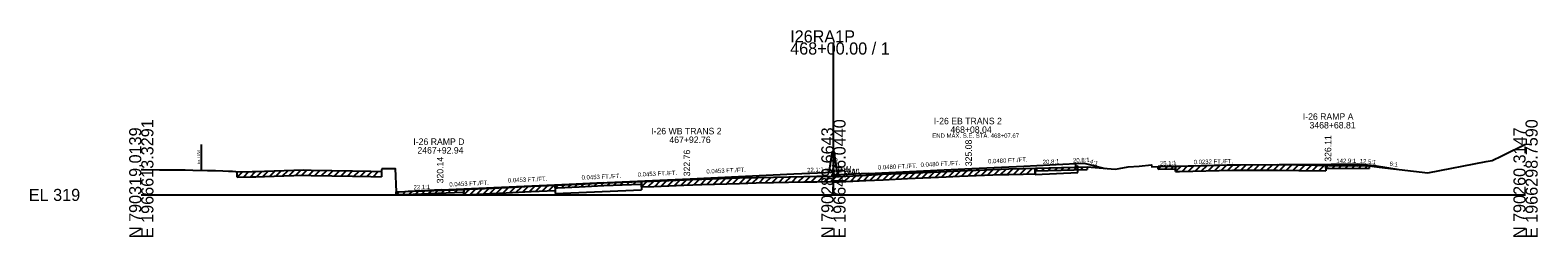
# Model space of a CAD drawing. Extents: x -44 to 4323, y -10 to 9601.
# Drawn here: x 3974.3 to 4322.8, y 6490.3 to 6538.1 of the extents above; entities that cross this region are included whole.
import ezdxf

# ---------------------------------------------------------------- set-up
doc = ezdxf.new("R2010")
doc.units = 0
for name, color, linetype in [('1', 7, 'Continuous'), ('DateStamp', 7, 'Continuous'), ('NotForConst', 7, 'Continuous'), ('QCQA', 7, 'Continuous'), ('RD_SHT_Bndy', 7, 'Continuous'), ('RD_SHT_Iplotshp', 7, 'Continuous'), ('RD_SHT_TX', 7, 'Continuous'), ('RD_XS_ExGround', 7, 'Continuous'), ('RD_XS_MatchLine', 7, 'Continuous'), ('RD_XS_MedBWall', 7, 'Continuous'), ('RD_XS_Misc_Line', 7, 'Continuous'), ('RD_XS_Pave', 7, 'Continuous'), ('RD_XS_PaveOvlay', 7, 'Continuous'), ('RD_XS_PaveShd', 7, 'Continuous'), ('RD_XS_TX_Elev_PR', 7, 'Continuous'), ('RD_XS_TX_Profile', 7, 'Continuous'), ('RD_XS_TX_ShdSlope', 7, 'Continuous'), ('RD_XS_TX_Slope', 7, 'Continuous'), ('seal', 7, 'Continuous'), ('TR SN EXTRUDED PANEL SIGNS - GROUND MOUNTED', 7, 'Continuous')]:
    doc.layers.add(name, color=color, linetype=linetype)

msp = doc.modelspace()

# ---------------------------------------------------------------- linework, layer by layer
at = {"layer": 'DateStamp'}
msp.add_lwpolyline([(4000, 6505.86), (4000.57, 6505.85), (4004.17, 6505.83), (4007.8, 6505.8), (4010.17, 6505.77), (4011.88, 6505.75), (4015.27, 6505.65), (4017.19, 6505.61), (4018.84, 6505.56), (4020.14, 6505.5), (4021.1, 6505.45), (4021.75, 6505.4), (4022.13, 6505.36), (4025.63, 6505.39), (4026.5, 6505.41), (4028.48, 6505.49), (4037.5, 6505.8), (4039.26, 6505.74), (4048.83, 6505.56), (4053.03, 6505.47), (4055.56, 6505.44), (4055.71, 6506.12), (4056.83, 6506.12), (4058.71, 6506.12), (4058.93, 6500.69), (4062.86, 6500.83), (4072.41, 6501.17), (4077.69, 6501.42), (4084.36, 6501.72), (4090.12, 6502), (4096.19, 6502.29), (4101.26, 6502.52), (4106.94, 6502.77), (4113.35, 6503.02), (4118.47, 6503.21), (4125.45, 6503.47), (4129.55, 6503.63), (4138.29, 6503.91), (4142.12, 6504.04), (4146.18, 6504.12), (4153.12, 6504.26), (4156.19, 6504.31), (4158.54, 6504.35), (4160.05, 6504.29), (4161.32, 6504.24), (4164.47, 6504.41), (4167.46, 6504.57), (4171.52, 6504.77), (4177.13, 6505.04), (4186.09, 6505.44), (4189.16, 6505.58), (4198.79, 6505.93), (4200.54, 6505.99), (4203.87, 6506.08), (4218.62, 6506.48), (4222.32, 6506.16), (4225.15, 6505.95), (4226.04, 6506.09), (4228.17, 6506.47), (4230.7, 6506.66), (4233.54, 6506.95), (4233.64, 6506.5), (4235.08, 6506.54), (4239.2, 6506.66), (4239.99, 6506.67), (4252.22, 6506.97), (4254.1, 6506.97), (4262.68, 6507), (4267.56, 6506.92), (4267.9, 6506.92), (4274.59, 6506.83), (4283.87, 6506.71), (4286.13, 6506.44), (4297.43, 6505.09), (4310.86, 6507.7), (4312.28, 6507.94), (4314.5, 6509.04), (4320, 6511.75)], dxfattribs=at)
at = {"layer": 'NotForConst'}
for p, q in [((4022.13, 6504.11), (4023.39, 6505.37)), ((4023.63, 6504.12), (4024.89, 6505.38)), ((4025.13, 6504.13), (4026.41, 6505.41)), ((4026.63, 6504.17), (4027.93, 6505.47)), ((4028.13, 6504.23), (4029.42, 6505.53)), ((4029.63, 6504.28), (4030.92, 6505.58)), ((4031.13, 6504.33), (4032.42, 6505.63)), ((4032.63, 6504.39), (4033.92, 6505.68)), ((4034.13, 6504.44), (4035.42, 6505.73)), ((4035.63, 6504.49), (4036.92, 6505.78)), ((4037.13, 6504.54), (4038.36, 6505.77)), ((4038.63, 6504.51), (4039.85, 6505.73)), ((4040.13, 6504.48), (4041.36, 6505.7)), ((4041.63, 6504.45), (4042.86, 6505.67)), ((4043.13, 6504.42), (4044.36, 6505.64)), ((4044.63, 6504.39), (4045.86, 6505.61)), ((4046.13, 6504.36), (4047.36, 6505.58)), ((4047.63, 6504.33), (4048.86, 6505.55)), ((4049.13, 6504.3), (4050.36, 6505.52)), ((4050.63, 6504.27), (4051.86, 6505.49)), ((4052.13, 6504.24), (4053.36, 6505.47)), ((4053.63, 6504.21), (4054.86, 6505.45)), ((4129.24, 6502.36), (4130.54, 6503.66)), ((4130.75, 6502.42), (4132.05, 6503.71)), ((4132.26, 6502.47), (4133.56, 6503.76)), ((4133.77, 6502.52), (4135.07, 6503.81)), ((4135.27, 6502.57), (4136.58, 6503.86)), ((4136.78, 6502.62), (4138.08, 6503.91)), ((4138.29, 6502.66), (4139.59, 6503.96)), ((4139.8, 6502.72), (4141.1, 6504.01)), ((4141.31, 6502.77), (4142.6, 6504.05)), ((4142.82, 6502.81), (4144.1, 6504.08)), ((4144.33, 6502.84), (4145.61, 6504.11)), ((4145.84, 6502.87), (4147.12, 6504.14)), ((4147.35, 6502.9), (4148.63, 6504.17)), ((4148.86, 6502.93), (4150.14, 6504.2)), ((4150.36, 6502.96), (4151.65, 6504.23)), ((4151.87, 6502.99), (4153.16, 6504.26)), ((4153.38, 6503.02), (4154.66, 6504.29)), ((4154.89, 6503.04), (4156.17, 6504.31)), ((4156.4, 6503.06), (4157.68, 6504.34)), ((4157.91, 6503.09), (4159.15, 6504.33)), ((4159.42, 6503.07), (4160.62, 6504.27)), ((4160.93, 6503), (4162.21, 6504.28)), ((4162.44, 6503.05), (4163.77, 6504.37)), ((4163.94, 6503.13), (4165.27, 6504.45)), ((4165.45, 6503.21), (4166.78, 6504.53)), ((4166.96, 6503.29), (4168.29, 6504.61)), ((4168.47, 6503.37), (4169.79, 6504.68)), ((4169.98, 6503.44), (4171.3, 6504.76)), ((4171.49, 6503.52), (4172.81, 6504.83)), ((4173, 6503.59), (4174.32, 6504.9)), ((4174.51, 6503.66), (4175.83, 6504.97)), ((4176.02, 6503.73), (4177.34, 6505.05)), ((4177.52, 6503.8), (4178.84, 6505.11)), ((4179.03, 6503.87), (4180.35, 6505.18)), ((4180.54, 6503.94), (4181.86, 6505.25)), ((4182.05, 6504.01), (4183.37, 6505.32)), ((4183.56, 6504.08), (4184.88, 6505.38)), ((4185.07, 6504.14), (4186.39, 6505.45)), ((4186.58, 6504.21), (4187.9, 6505.52)), ((4188.09, 6504.28), (4189.4, 6505.59)), ((4189.6, 6504.34), (4190.9, 6505.64)), ((4191.11, 6504.4), (4192.41, 6505.7)), ((4192.61, 6504.46), (4193.92, 6505.75)), ((4194.12, 6504.51), (4195.43, 6505.81)), ((4195.63, 6504.57), (4196.94, 6505.87)), ((4197.14, 6504.62), (4198.45, 6505.92)), ((4198.65, 6504.68), (4199.95, 6505.97)), ((4200.16, 6504.73), (4201.45, 6506.01)), ((4201.67, 6504.77), (4202.96, 6506.05)), ((4203.18, 6504.81), (4204.47, 6506.09)), ((4204.69, 6504.85), (4205.98, 6506.13)), ((4206.61, 6505.53), (4207.26, 6506.17)), ((4208.11, 6505.57), (4208.76, 6506.21)), ((4209.61, 6505.61), (4210.26, 6506.25)), ((4211.11, 6505.65), (4211.76, 6506.29)), ((4212.61, 6505.69), (4213.26, 6506.33)), ((4214.12, 6505.73), (4214.76, 6506.37)), ((4215.62, 6505.77), (4216.26, 6506.41)), ((4217.12, 6505.81), (4217.76, 6506.45)), ((4235.08, 6505.92), (4235.72, 6506.56)), ((4236.58, 6505.96), (4237.22, 6506.6)), ((4238.08, 6506), (4238.72, 6506.64)), ((4239.08, 6505.4), (4240.37, 6506.68)), ((4240.59, 6505.44), (4241.88, 6506.72)), ((4242.1, 6505.47), (4243.39, 6506.76)), ((4243.61, 6505.51), (4244.9, 6506.79)), ((4245.12, 6505.55), (4246.41, 6506.83)), ((4246.63, 6505.58), (4247.92, 6506.86)), ((4248.14, 6505.62), (4249.42, 6506.9)), ((4249.65, 6505.65), (4250.93, 6506.93)), ((4251.15, 6505.69), (4252.44, 6506.97)), ((4252.66, 6505.72), (4253.92, 6506.97)), ((4254.17, 6505.72), (4255.43, 6506.97)), ((4255.68, 6505.72), (4256.94, 6506.98)), ((4257.19, 6505.73), (4258.45, 6506.98)), ((4258.7, 6505.73), (4259.96, 6506.99)), ((4260.21, 6505.74), (4261.47, 6506.99)), ((4261.72, 6505.74), (4262.97, 6506.99)), ((4263.23, 6505.74), (4264.46, 6506.97)), ((4264.73, 6505.71), (4265.97, 6506.95)), ((4266.24, 6505.69), (4267.48, 6506.92)), ((4267.75, 6505.67), (4268.99, 6506.9)), ((4269.26, 6505.65), (4270.5, 6506.89)), ((4270.77, 6505.63), (4272.01, 6506.87)), ((4272.28, 6505.61), (4273.52, 6506.85)), ((4273.86, 6506.22), (4274.47, 6506.84)), ((4275.36, 6506.2), (4275.97, 6506.82)), ((4276.86, 6506.18), (4277.47, 6506.8)), ((4278.36, 6506.16), (4278.97, 6506.78)), ((4279.86, 6506.14), (4280.47, 6506.75)), ((4281.36, 6506.12), (4281.97, 6506.73)), ((4282.86, 6506.1), (4283.47, 6506.71)), ((4058.93, 6500.06), (4059.58, 6500.71)), ((4060.43, 6500.12), (4061.08, 6500.77)), ((4061.93, 6500.17), (4062.58, 6500.82)), ((4063.43, 6500.23), (4064.08, 6500.87)), ((4064.93, 6500.28), (4065.58, 6500.93)), ((4066.43, 6500.33), (4067.08, 6500.98)), ((4067.93, 6500.39), (4068.58, 6501.03)), ((4069.43, 6500.44), (4070.08, 6501.09)), ((4070.93, 6500.49), (4071.58, 6501.14)), ((4072.43, 6500.55), (4073.09, 6501.2)), ((4074.54, 6500.02), (4075.86, 6501.34)), ((4076.05, 6500.1), (4077.37, 6501.41)), ((4077.56, 6500.17), (4078.87, 6501.48)), ((4079.07, 6500.24), (4080.38, 6501.54)), ((4080.57, 6500.3), (4081.89, 6501.61)), ((4082.08, 6500.37), (4083.4, 6501.68)), ((4083.59, 6500.44), (4084.91, 6501.75)), ((4085.1, 6500.51), (4086.42, 6501.82)), ((4086.61, 6500.58), (4087.93, 6501.89)), ((4088.12, 6500.65), (4089.44, 6501.97)), ((4089.63, 6500.72), (4090.95, 6502.04)), ((4091.14, 6500.8), (4092.46, 6502.11)), ((4092.65, 6500.87), (4093.97, 6502.18)), ((4094.15, 6500.94), (4095.48, 6502.25)), ((4095.71, 6501.64), (4096.36, 6502.29)), ((4097.21, 6501.71), (4097.86, 6502.36)), ((4098.71, 6501.78), (4099.36, 6502.43)), ((4100.21, 6501.84), (4100.86, 6502.5)), ((4101.71, 6501.91), (4102.36, 6502.56)), ((4103.21, 6501.98), (4103.86, 6502.63)), ((4104.71, 6502.04), (4105.36, 6502.7)), ((4106.21, 6502.11), (4106.86, 6502.76)), ((4107.71, 6502.17), (4108.36, 6502.82)), ((4109.21, 6502.23), (4109.86, 6502.88)), ((4110.71, 6502.29), (4111.36, 6502.94)), ((4112.21, 6502.35), (4112.86, 6503)), ((4113.71, 6502.41), (4114.36, 6503.06)), ((4115.66, 6501.85), (4116.96, 6503.15)), ((4117.17, 6501.91), (4118.47, 6503.21)), ((4118.68, 6501.96), (4119.98, 6503.26)), ((4120.19, 6502.02), (4121.49, 6503.32)), ((4121.69, 6502.08), (4123, 6503.38)), ((4123.2, 6502.13), (4124.51, 6503.43)), ((4124.71, 6502.19), (4126.02, 6503.49)), ((4126.22, 6502.25), (4127.53, 6503.55)), ((4127.73, 6502.31), (4129.04, 6503.61))]:
    msp.add_line(p, q, dxfattribs=at)
at = {"layer": 'QCQA'}
for p, q in [((4125.45, 6503.47), (4129.55, 6503.63)), ((4129.55, 6503.63), (4138.29, 6503.91)), ((4138.29, 6503.91), (4142.12, 6504.04)), ((4142.12, 6504.04), (4146.18, 6504.12)), ((4146.18, 6504.12), (4153.12, 6504.26)), ((4153.12, 6504.26), (4156.19, 6504.31)), ((4156.19, 6504.31), (4158.54, 6504.35)), ((4158.54, 6504.35), (4160.05, 6504.29)), ((4160.05, 6504.29), (4161.32, 6504.24)), ((4161.32, 6504.24), (4164.47, 6504.41)), ((4164.47, 6504.41), (4167.46, 6504.57)), ((4167.46, 6504.57), (4171.52, 6504.77)), ((4171.52, 6504.77), (4177.13, 6505.04)), ((4177.13, 6505.04), (4186.09, 6505.44)), ((4186.09, 6505.44), (4189.16, 6505.58)), ((4189.16, 6505.58), (4198.79, 6505.93)), ((4198.79, 6505.93), (4200.54, 6505.99)), ((4200.54, 6505.99), (4203.87, 6506.08)), ((4203.87, 6506.08), (4206.61, 6506.15)), ((4239.08, 6506.65), (4235.08, 6506.54)), ((4239.08, 6506.65), (4239.2, 6506.66)), ((4239.2, 6506.66), (4239.99, 6506.67)), ((4239.99, 6506.67), (4252.22, 6506.97)), ((4252.22, 6506.97), (4254.1, 6506.97)), ((4254.1, 6506.97), (4262.68, 6507)), ((4262.68, 6507), (4267.56, 6506.92)), ((4267.56, 6506.92), (4267.9, 6506.92)), ((4267.9, 6506.92), (4273.86, 6506.84)), ((4273.86, 6506.84), (4281.1, 6506.75)), ((4106.94, 6502.77), (4095.71, 6502.26)), ((4095.71, 6502.26), (4095.71, 6500.3)), ((4106.94, 6502.77), (4115.66, 6503.1)), ((4115.66, 6503.1), (4118.47, 6503.21)), ((4115.66, 6503.1), (4115.66, 6501.2)), ((4118.47, 6503.21), (4125.45, 6503.47))]:
    msp.add_line(p, q, dxfattribs=at)
at = {"layer": 'RD_SHT_Bndy'}
for p, q in [((4160, 6500), (4160, 6535.24)), ((4000, 6500), (4160, 6500)), ((4160, 6500), (4320, 6500))]:
    msp.add_line(p, q, dxfattribs=at)
at = {"layer": 'RD_SHT_Iplotshp'}
for p, q in [((4022.13, 6504.11), (4022.13, 6505.36)), ((4022.13, 6504.11), (4025.63, 6504.14)), ((4025.63, 6504.14), (4026.5, 6504.16)), ((4026.5, 6504.16), (4028.48, 6504.24)), ((4028.48, 6504.24), (4037.5, 6504.55)), ((4037.5, 6504.55), (4039.26, 6504.49)), ((4039.26, 6504.49), (4048.83, 6504.31)), ((4048.83, 6504.31), (4053.03, 6504.22)), ((4053.03, 6504.22), (4055.56, 6504.19)), ((4055.56, 6505.44), (4055.56, 6504.19)), ((4171.52, 6503.52), (4177.13, 6503.79)), ((4177.13, 6503.79), (4186.09, 6504.19)), ((4186.09, 6504.19), (4189.16, 6504.33)), ((4189.16, 6504.33), (4198.79, 6504.68)), ((4198.79, 6504.68), (4200.54, 6504.74)), ((4200.54, 6504.74), (4203.87, 6504.83)), ((4203.87, 6504.83), (4206.61, 6504.9)), ((4206.61, 6506.15), (4206.61, 6504.9)), ((4206.61, 6505.53), (4206.61, 6506.15)), ((4206.61, 6505.53), (4218.62, 6505.85)), ((4218.62, 6506.48), (4218.62, 6505.85)), ((4235.08, 6505.92), (4235.08, 6506.54)), ((4235.08, 6505.92), (4239.08, 6506.03)), ((4239.08, 6505.4), (4239.08, 6506.65)), ((4239.08, 6506.65), (4239.08, 6506.03)), ((4239.08, 6505.4), (4239.2, 6505.41)), ((4239.2, 6505.41), (4239.99, 6505.42)), ((4239.99, 6505.42), (4252.22, 6505.72)), ((4252.22, 6505.72), (4254.1, 6505.72)), ((4254.1, 6505.72), (4262.68, 6505.75)), ((4262.68, 6505.75), (4267.56, 6505.67)), ((4267.56, 6505.67), (4267.9, 6505.67)), ((4267.9, 6505.67), (4273.86, 6505.59)), ((4273.86, 6506.84), (4273.86, 6505.59)), ((4273.86, 6506.22), (4273.86, 6506.84)), ((4273.86, 6506.22), (4274.59, 6506.21)), ((4274.59, 6506.21), (4283.87, 6506.08)), ((4283.87, 6506.71), (4283.87, 6506.08)), ((4058.93, 6500.06), (4058.93, 6500.69)), ((4058.93, 6500.06), (4062.86, 6500.21)), ((4062.86, 6500.21), (4072.41, 6500.54)), ((4072.41, 6500.54), (4074.54, 6500.65)), ((4074.54, 6500.02), (4074.54, 6501.27)), ((4074.54, 6501.27), (4074.54, 6500.65)), ((4074.54, 6500.02), (4077.69, 6500.17)), ((4077.69, 6500.17), (4084.36, 6500.47)), ((4084.36, 6500.47), (4090.12, 6500.75)), ((4090.12, 6500.75), (4095.71, 6501.01)), ((4095.71, 6502.26), (4095.71, 6501.01)), ((4095.71, 6501.64), (4095.71, 6502.26)), ((4095.71, 6501.64), (4096.19, 6501.66)), ((4096.19, 6501.66), (4101.26, 6501.89)), ((4101.26, 6501.89), (4106.94, 6502.14)), ((4106.94, 6502.14), (4113.35, 6502.4)), ((4113.35, 6502.4), (4115.66, 6502.48)), ((4115.66, 6501.85), (4115.66, 6503.1)), ((4115.66, 6503.1), (4115.66, 6502.48)), ((4115.66, 6501.85), (4118.47, 6501.96)), ((4118.47, 6501.96), (4125.45, 6502.22)), ((4125.45, 6502.22), (4129.55, 6502.38)), ((4129.55, 6502.38), (4138.29, 6502.66)), ((4138.29, 6502.66), (4142.12, 6502.79)), ((4142.12, 6502.79), (4146.18, 6502.87)), ((4146.18, 6502.87), (4153.12, 6503.01)), ((4153.12, 6503.01), (4156.19, 6503.06)), ((4156.19, 6503.06), (4158.54, 6503.1)), ((4158.54, 6503.1), (4160.05, 6503.04)), ((4160.05, 6503.04), (4161.32, 6502.99)), ((4161.32, 6502.99), (4164.47, 6503.16)), ((4164.47, 6503.16), (4167.46, 6503.32)), ((4167.46, 6503.32), (4171.52, 6503.52))]:
    msp.add_line(p, q, dxfattribs=at)
at = {"layer": 'RD_XS_Misc_Line'}
for p, q in [((4216, 6506.67), (4216, 6507.23)), ((4281.1, 6506.75), (4281.1, 6507.15)), ((4206.61, 6504.74), (4206.61, 6506.15)), ((4206.61, 6504.74), (4216.5, 6505.21)), ((4216, 6506.67), (4216.5, 6506.69)), ((4216.5, 6505.21), (4216.5, 6506.69)), ((4095.71, 6500.3), (4115.66, 6501.2))]:
    msp.add_line(p, q, dxfattribs=at)
at = {"layer": 'RD_XS_Pave'}
for p, q in [((4218, 6507.32), (4222.78, 6506.13)), ((4285.11, 6506.83), (4290.79, 6505.88))]:
    msp.add_line(p, q, dxfattribs=at)
at = {"layer": 'RD_XS_PaveOvlay'}
msp.add_line((4013.82, 6511.69), (4013.82, 6505.69), dxfattribs=at)
at = {"layer": 'RD_XS_PaveShd'}
for p, q in [((4216, 6507.23), (4218, 6507.32)), ((4281.1, 6507.15), (4285.11, 6506.83))]:
    msp.add_line(p, q, dxfattribs=at)
at = {"layer": 'RD_XS_TX_Elev_PR'}
for p, q in [((4204, 6506.65), (4216, 6507.23)), ((4275.08, 6507.11), (4281.1, 6507.15)), ((4150.88, 6504.84), (4160, 6505.26)), ((4160, 6505.26), (4160, 6504.54)), ((4168, 6504.92), (4160, 6504.54)), ((4238.98, 6506.66), (4235.08, 6506.54)), ((4069.35, 6501.14), (4061.72, 6500.79))]:
    msp.add_line(p, q, dxfattribs=at)
at = {"layer": 'RD_XS_TX_ShdSlope'}
for p, q in [((4159, 6505.21), (4159.67, 6509.76)), ((4160.33, 6509.84), (4159.67, 6509.84)), ((4159.67, 6509.76), (4159.67, 6509.84)), ((4160.33, 6509.04), (4160.33, 6509.84)), ((4161, 6504.59), (4160.33, 6509.04))]:
    msp.add_line(p, q, dxfattribs=at)
at = {"layer": 'RD_XS_TX_Slope'}
for p, q in [((4251, 6506.94), (4275.08, 6507.11)), ((4069.35, 6501.14), (4126.88, 6503.75)), ((4126.88, 6503.75), (4150.88, 6504.84)), ((4168, 6504.92), (4192, 6506.08)), ((4192, 6506.08), (4204, 6506.65)), ((4238.98, 6506.66), (4251, 6506.94))]:
    msp.add_line(p, q, dxfattribs=at)

# ---------------------------------------------------------------- texts
at = {"layer": '1'}
for s, p in [('I-26 EB TRANS 2', (4183.22, 6516.33)), ('I-26 RAMP A', (4268.51, 6517.36)), ('I-26 WB TRANS 2', (4117.87, 6514)), ('468+08.04', (4187.05, 6514.33)), ('3468+68.81', (4270.06, 6515.36)), ('I-26 RAMP D', (4062.89, 6511.56)), ('2467+92.94', (4063.83, 6509.56)), ('467+92.76', (4122.08, 6512))]:
    msp.add_text(s, height=1.5, dxfattribs=at).set_placement(p)
at = {"layer": 'RD_SHT_Bndy'}
for s, p in [('468+00.00 / 1', (4150, 6532.44)), ('I26RA1P', (4150, 6535.24)), ('EL 319', (3974, 6498.6))]:
    msp.add_text(s, height=2.8, dxfattribs=at).set_placement(p)
for s, p in [('N 790319.0139', (4000, 6490)), ('E 1966613.3291', (4002.8, 6490)), ('N 790289.6643', (4160, 6490)), ('E 1966456.0440', (4162.8, 6490)), ('N 790260.3147', (4320, 6490)), ('E 1966298.7590', (4322.8, 6490))]:
    msp.add_text(s, height=2.8, rotation=90, dxfattribs=at).set_placement(p)
at = {"layer": 'RD_SHT_TX'}
msp.add_text('323.30', height=1, rotation=90, dxfattribs=at).set_placement((4161, 6504.3))
at = {"layer": 'RD_XS_ExGround'}
for s, rotation, p in [('20.8:1', 2.7481, (4208.41, 6507.11)), ('22.1:1', 2.5954, (4153.95, 6505.23)), ('20.8:1', 2.7481, (4162.41, 6504.91)), ('22.1:1', 2.5937, (4062.97, 6501.24))]:
    msp.add_text(s, height=1, rotation=rotation, dxfattribs=at).set_placement(p)
at = {"layer": 'RD_XS_MatchLine'}
msp.add_text('END MAX. S.E. STA. 468+07.67', height=1, dxfattribs=at).set_placement((4182.85, 6513.2))
at = {"layer": 'RD_XS_MedBWall'}
for s, rotation, p in [('20.8:1', 2.7481, (4215.41, 6507.45)), ('12.5:1', 355.4381, (4281.64, 6507.36))]:
    msp.add_text(s, height=1, rotation=rotation, dxfattribs=at).set_placement(p)
at = {"layer": 'RD_XS_PaveOvlay'}
msp.add_text('Ex. R/W ', height=0.65, rotation=90, dxfattribs=at).set_placement((4013.57, 6507.08))
at = {"layer": 'RD_XS_TX_Profile'}
for s, p in [('WBW', (4159, 6505.21)), ('EBW', (4161, 6504.59))]:
    msp.add_text(s, height=1.5, dxfattribs=at).set_placement(p)
at = {"layer": 'seal'}
for s, p in [(' 325.08', (4192, 6506.08)), (' 326.11', (4275.08, 6507.11)), ('320.14', (4069.83, 6502.67)), (' 322.76', (4126.88, 6503.75))]:
    msp.add_text(s, height=1.5, rotation=90, dxfattribs=at).set_placement(p)
at = {"layer": 'TR SN EXTRUDED PANEL SIGNS - GROUND MOUNTED'}
for s, rotation, p in [('0.0480 FT./FT.', 2.7481, (4170.31, 6505.85)), ('0.0480 FT./FT.', 2.7481, (4180.17, 6506.47)), ('0.0480 FT./FT.', 2.7481, (4195.77, 6507.26)), ('4:1', 340.9653, (4219.18, 6507.35)), ('25.1:1', 2.2846, (4235.49, 6506.77)), ('0.0232 FT./FT.', 1.3277, (4243.28, 6507.1)), ('142.9:1', 0.4009, (4276.26, 6507.36)), ('6:1', 350.5623, (4288.5, 6506.77)), ('0.0453 FT./FT.', 2.5937, (4084.76, 6502.85)), ('0.0453 FT./FT.', 2.5937, (4101.8, 6503.5)), ('0.0453 FT./FT.', 2.5937, (4114.77, 6504.21)), ('0.0453 FT./FT.', 2.5954, (4130.65, 6504.93)), ('0.0453 FT./FT.', 2.5937, (4071.23, 6501.93))]:
    msp.add_text(s, height=1, rotation=rotation, dxfattribs=at).set_placement(p)

doc.saveas('drawing.dxf')
